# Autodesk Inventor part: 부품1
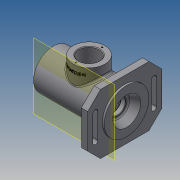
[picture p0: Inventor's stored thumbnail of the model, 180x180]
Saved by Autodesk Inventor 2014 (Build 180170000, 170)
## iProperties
Created: 2017-10
Part Number: 부품1
Material: 일반
Document SubType Name: Modeling
Designer: NET
Density: 1 g/cm^3
Appearance: 기본값
Author: NET
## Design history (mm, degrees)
sketch "스케치1"
  geometry: L1 (-58, 47)-(58, 47); L2 (58, 47)-(58, -47); L3 (58, -47)-(-58, -47); L4 (-58, -47)-(-58, 47); C1 r 31 at (0, 0); C2 r 35 at (0, 0); 3 further points
  constraints: 8 end point, 2 centre point, 2 coincident, 2 midpoint, 2 parallel, 1 horizontal, 1 horizontal alignment, 1 perpendicular, 1 vertical alignment
  dimensions: "d0" = 62 diameter of C1; "d1" = 116 distance of L1.start L1.end; "d2" = 94 distance of L1.end L2.end; "d3" = 70 diameter of C2
extrude "돌출1" new body sketch "스케치1" distance "d4" = 10; taper "d5" = 0 deg
extrude "돌출2" join sketch "스케치1" distance "d6" = 13; taper "d7" = 0 deg
extrude "돌출3" join sketch "스케치1" distance "d8" = 102; taper "d9" = 0 deg
chamfer "모따기1" distance "d10" = 20; stored, may be unused: second distance "d11" = 2, angle "d12" = 45 deg
node "작업 평면1"
sketch "스케치2"
  geometry: L1 (38, 0)-(-38, 0) reference; L2 (31, 102)-(-31, 102) reference; C1 r 25 at (0, 46); 2 further points
  constraints: 1 centre point, 1 midpoint, 1 vertical alignment
  dimensions: "d13" = 50 diameter of C1; "d14" = 56 distance from line of C1.centre L2
extrude "돌출4" join sketch "스케치2" stored distance "d15" = 32; taper "d16" = 0 deg
sketch "스케치3"
  geometry: L1 (-38, -47)-(38, -47) reference; L2 (-46, 20)-(-46, -20); L3 (-50, 20)-(-50, -20); L4 (-42, -20)-(-42, 20); L5 (46, 20)-(46, -20); L6 (42, 20)-(42, -20); L7 (50, -20)-(50, 20); C1 r 35 at (0, 0) reference; A1 r 4 centre (-46, 20) between (-42, 20) and (-50, 20); A2 r 4 centre (-46, -20) between (-50, -20) and (-42, -20); A3 r 4 centre (46, 20) between (50, 20) and (42, 20); A4 r 4 centre (46, -20) between (42, -20) and (50, -20); 2 further points
  constraints: 16 end point, 8 point on circle, 8 tangent, 4 centre point, 4 parallel, 2 horizontal alignment, 2 midpoint, 1 perpendicular
  dimensions: "d17" = 46 distance of point (-46, 0) C1.centre; "d18" = 92 distance of point (46, 0) point (-46, 0); "d19" = 40 distance of L5.end L5.start; "d20" = 4 radius of A3; "d21" = 4 radius of A1
extrude "돌출5" cut sketch "스케치3" distance "d22" = 32; taper "d23" = 0 deg
extrude "돌출6" join sketch "스케치1" distance "d24" = 13; taper "d25" = 0 deg
sketch "스케치4"
  geometry: L1 (31, 102)-(-31, 102) reference; L2 (31, 0)-(31, 102) reference; L3 (-31, 0)-(31, 0) reference; L4 (21, 93)-(24, 93); L5 (24, 93)-(24, 90); L6 (24, 90)-(20, 90); L7 (20, 90)-(20, 81); L8 (20, 81)-(17.5, 81); L9 (17.5, 81)-(17.5, 77.75); L10 (17.5, 77.75)-(18.5, 77.75); L11 (18.5, 77.75)-(18.5, 76); L12 (18.5, 76)-(17.5, 76); L13 (17.5, 76)-(17.5, 65); L14 (17.5, 65)-(23, 65); L15 (26, 62)-(26, 30); L16 (23, 27)-(17.5, 27); L17 (17.5, 27)-(17.5, 16.3); L18 (17.2, 16)-(16.5, 16); L19 (16.5, 16)-(16.5, 14); L20 (13.5, 11)-(10, 11); L21 (10, 11)-(10, 8.3); L22 (10, 8.3)-(12.2, 8.3); L23 (12.5, 8)-(12.5, 1.7); L24 (12.904, 1)-(14.022, 1); L25 (0, 102)-(0, 0); L26 (21, 93)-(21, 102); L27 (16.779, -0.818)-(22, -13); L28 (-35, -13)-(35, -13) reference; L29 (22, -13)-(0, -13); L30 (0, 0)-(0, -13); L31 (12.5, 1.7)-(12.904, 1); A1 r 3 centre (23, 30) between (23, 27) and (26, 30); A2 r 3 centre (23, 62) between (26, 62) and (23, 65); A3 r 3 centre (13.5, 14) between (13.5, 11) and (16.5, 14); A4 r 3 centre (14.022, -2) between (16.779, -0.818) and (14.022, 1); A5 r 0.3 centre (17.2, 16.3) between (17.2, 16) and (17.5, 16.3); A6 r 0.3 centre (12.2, 8) between (12.5, 8) and (12.2, 8.3); 7 further points
  constraints: 54 end point, 16 point on line, 14 perpendicular, 12 point on circle, 12 tangent, 10 parallel, 6 centre point, 4 equal radius, 2 collinear, 2 midpoint
  dimensions: "d26" = 42 diameter of L26 L25; "d27" = 40 diameter of L7 L25; "d28" = 48 diameter of L5 L25; "d29" = 35 diameter of L9 L25; "d30" = 37 diameter of L11 L25; "d31" = 52 diameter of L15 L25; "d33" = 33 diameter of L19 L25; "d34" = 20 diameter of L21 L25; "d35" = 25 diameter of L23 L25; "d36" = 32 diameter of point (16, 1) L25; "d38" = 12 distance from line of L26.end L6; "d39" = 3 distance of L4.end L5.end; "d40" = 21 distance from line of L1 L7.end; "d42" = 26 distance from line of L1 L11.end; "d43" = 1.75 distance of L10.end L11.end; "d44" = 38 distance of point (26, 65) point (26, 27); "d45" = 60 vertical distance of L12.end L18.end; "d46" = 14 distance from line of L24 L27.end; "d48" = 2.7 distance between parallel lines of L20 L22; "d49" = 7.3 distance between parallel lines of L22 L24; "d50" = 11 distance from line of L12.end L14; "d51" = 44 diameter of L27.end L25; "d53" = 3 radius of A1; "d54" = 0.3 radius of A5; "d55" = 0.7 distance of L23.end point (12.5, 1); "d56" = 30 deg angle of L23 L31
revolve "회전1" sketch "스케치4" stored, may be unused: angle "d52" = 90 deg
sketch "스케치5"
  geometry: C1 r 25 at (0, 0) reference; C2 r 16 at (0, 0); 1 further point
  constraints: 1 centre point, 1 coincident
  dimensions: "d57" = 32 diameter of C2
extrude "돌출7" cut sketch "스케치5" distance "d58" = 50; taper "d59" = 0 deg
chamfer "모따기2" distance "d60" = 1; stored, may be unused: second distance "d61" = 2, angle "d62" = 45 deg
feature "스레드1" dims "d63" = 10, "d64" = 0
sketch "스케치6"
  geometry: C1 r 25 at (0, 0) reference; 2 further points
  constraints: 1 horizontal alignment
  dimensions: "d65" = 20.5 distance of C1.centre point (-20.5, 0)
hole "구멍1" sketch "스케치6" at (-20.5, 0) diameter "d66" = 2.459; stored, may be unused: countersink angle "d70" = 90 deg, drill point angle "d72" = 118 deg; dims "d67" = 6, "d68" = 4, "d69" = 2, "d71" = 8
fillet "모깎기1" dims "d76" = 3
chamfer "모따기3" distance "d77" = 1; stored, may be unused: second distance "d78" = 2, angle "d79" = 45 deg
node "작업 평면2"
sketch "스케치7"
  geometry: L1 (16, -25)-(16, 25) reference; 3 further points
  constraints: 1 horizontal alignment, 1 midpoint, 1 other
  dimensions: "d80" = 10 distance from line of L1 point (6, 0)
feature "엠보싱1" sketch "스케치7" dims "d1" = 116, "d2" = 94, "d81" = 0.5, "d82" = 0
node "솔리드1"
pattern_circular "원형 패턴1" dims angle "d74" = 360 deg
